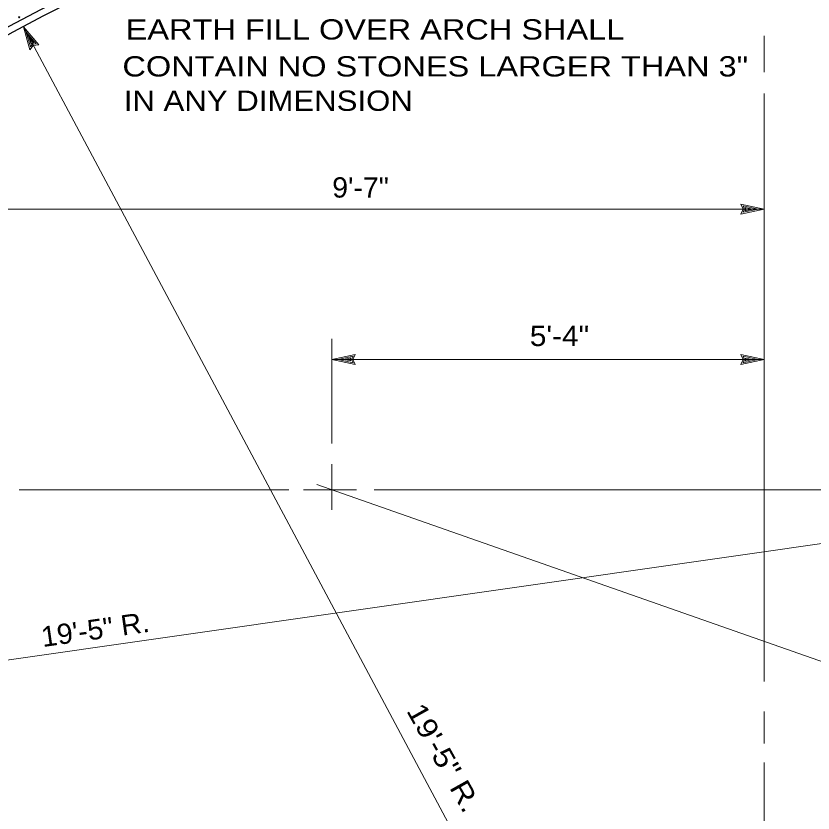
# Model space of a CAD drawing. Extents: x -24.3 to 17.7, y -17.6 to 12.4.
# Drawn here: x -14.525 to -9.607, y -10.053 to -5.135 of the extents above; entities that cross this region are included whole.
import ezdxf
from ezdxf.enums import TextEntityAlignment as Align

# ---------------------------------------------------------------- set-up
doc = ezdxf.new("R2010")
doc.units = 0
doc.header["$LTSCALE"] = 0.05
doc.layers.add('1', color=7, linetype='Continuous', lineweight=13)

msp = doc.modelspace()

# ---------------------------------------------------------------- linework, layer by layer
at = {"layer": '1'}
for p, q in [((-14.47869, -5.2016), (-14.43869, -5.3436)), ((-14.46169, -5.2346), (-14.39969, -5.3076)), ((-14.46169, -5.2346), (-14.43469, -5.3266)), ((-9.90869, -5.4826), (-9.90869, -5.2586)), ((-14.44469, -5.2656), (-14.43069, -5.3096)), ((-14.44469, -5.2656), (-14.41469, -5.3006)), ((-14.42169, -5.3096), (-14.43469, -5.3266)), ((-14.42469, -5.3026), (-14.43069, -5.3096)), ((-14.41469, -5.3006), (-14.42469, -5.3026)), ((-14.39969, -5.3076), (-14.42169, -5.3096)), ((-9.90869, -9.2416), (-9.90869, -5.6136)), ((-14.70069, -6.3266), (-9.90769, -6.3266)), ((-9.90769, -6.3266), (-10.05169, -6.2956)), ((-9.90769, -6.3266), (-10.05169, -6.3576)), ((-9.94469, -6.3266), (-10.03869, -6.3066)), ((-10.02969, -6.3266), (-10.03869, -6.3066)), ((-9.94469, -6.3266), (-10.03869, -6.3466)), ((-10.03869, -6.3466), (-10.02969, -6.3266)), ((-9.98069, -6.3266), (-10.02569, -6.3176)), ((-10.02169, -6.3266), (-10.02569, -6.3176)), ((-9.98069, -6.3266), (-10.02569, -6.3366)), ((-10.02569, -6.3366), (-10.02169, -6.3266)), ((-12.57569, -7.7726), (-12.57569, -7.1266)), ((-12.57569, -7.2546), (-12.43169, -7.2236)), ((-9.90769, -7.2546), (-10.05169, -7.2236)), ((-12.57569, -7.2546), (-9.90769, -7.2546)), ((-12.57569, -7.2546), (-12.43169, -7.2856)), ((-12.53869, -7.2546), (-12.44469, -7.2346)), ((-12.53869, -7.2546), (-12.44469, -7.2746)), ((-12.50269, -7.2546), (-12.45769, -7.2446)), ((-12.50269, -7.2546), (-12.45769, -7.2636)), ((-12.45769, -7.2446), (-12.46169, -7.2546)), ((-12.46169, -7.2546), (-12.45769, -7.2636)), ((-12.44469, -7.2346), (-12.45369, -7.2546)), ((-12.45369, -7.2546), (-12.44469, -7.2746)), ((-9.90769, -7.2546), (-10.05169, -7.2856)), ((-9.94469, -7.2546), (-10.03869, -7.2346)), ((-10.02969, -7.2546), (-10.03869, -7.2346)), ((-9.94469, -7.2546), (-10.03869, -7.2746)), ((-10.03869, -7.2746), (-10.02969, -7.2546)), ((-9.98069, -7.2546), (-10.02569, -7.2456)), ((-10.02169, -7.2546), (-10.02569, -7.2456)), ((-9.98069, -7.2546), (-10.02569, -7.2646)), ((-10.02569, -7.2646), (-10.02169, -7.2546)), ((-12.57569, -8.1816), (-12.57569, -7.8996)), ((-14.50569, -8.0586), (-12.84169, -8.0586)), ((-12.75069, -8.0586), (-12.42369, -8.0586)), ((-6.97269, -10.0246), (-12.66869, -8.0256)), ((-12.31469, -8.0586), (-7.82569, -8.0586)), ((-9.90869, -9.6236), (-9.90869, -9.4256)), ((-9.90869, -11.2926), (-9.90869, -9.7416))]:
    msp.add_line(p, q, dxfattribs=at)
for points in [[(-9.90869, -13.7666), (-14.47869, -5.2016), (-14.38369, -5.3136)], [(-14.38369, -5.3136), (-14.41769, -5.3166), (-14.43869, -5.3436)], [(-10.05169, -6.3576), (-10.03769, -6.3266), (-10.05169, -6.2956)], [(-12.43169, -7.2236), (-12.44569, -7.2546), (-12.43169, -7.2856)], [(-10.05169, -7.2856), (-10.03769, -7.2546), (-10.05169, -7.2236)], [(-7.03769, -8.0296), (-16.85269, -9.4346), (-16.71469, -9.3836)]]:
    msp.add_lwpolyline(points, dxfattribs=at)
msp.add_circle((-14.50469, -5.1436), 0.00361, dxfattribs=at)
at = {"layer": '1', "lineweight": 25}
for radius in [9.74984, 9.70818]:
    msp.add_arc((-9.90906, -13.7666), radius, 49.71979, 130.09764, dxfattribs=at)
at = {"layer": '1'}
msp.add_arc((-9.90869, -13.7666), 9.22657, 50.60311, 90, dxfattribs=at)

# ---------------------------------------------------------------- texts
for s, width, p in [('EARTH FILL OVER ARCH SHALL', 1.2, (-13.84769, -5.2806)), ('CONTAIN NO STONES LARGER THAN 3"', 1.2, (-13.86769, -5.5086)), ('IN ANY DIMENSION', 1.15, (-13.85969, -5.7206))]:
    msp.add_text(s, height=0.125, dxfattribs=dict(at, width=width)).set_placement(p)
for s, width, p in [('9\'-7"', 1.05, (-12.39869, -6.2556)), ('5\'-4"', 1.1, (-11.17119, -7.1716))]:
    msp.add_text(s, height=0.125, dxfattribs=dict(at, width=width)).set_placement(p, align=Align.CENTER)
for rotation, width, p in [(8.146, 1.05, (-14.0269, -8.98123)), (299.226, 1.15, (-11.93885, -9.74182))]:
    msp.add_text('19\'-5" R.', height=0.125, rotation=rotation, dxfattribs=dict(at, width=width)).set_placement(p, align=Align.CENTER)

doc.saveas('drawing.dxf')
